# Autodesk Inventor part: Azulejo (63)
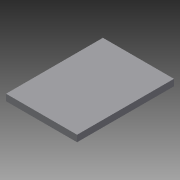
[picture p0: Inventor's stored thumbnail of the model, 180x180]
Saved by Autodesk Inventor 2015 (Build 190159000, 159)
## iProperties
Created: 2015-04
Part Number: Azulejo (63)
Material: Genérico
Document SubType Name: Modeling
Designer: Felipe
Density: 1 g/cm^3
Appearance: Padrão
Author: Felipe
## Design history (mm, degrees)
sketch "Sketch1"
  geometry: L1 (331.131, 3222.232)-(331.131, 2322.232); L2 (-328.869, 3222.232)-(331.131, 3222.232); L3 (-328.869, 2322.232)-(331.131, 2322.232); L4 (-328.869, -3617.768)-(-328.869, 3222.232); 1 further point
  constraints: 8 end point, 1 point on line
  dimensions: "d2" = 660 distance between parallel lines of L1 L4; "d3" = 900 distance between parallel lines of L2 L3
extrude "Extrusion1" new body sketch "Sketch1" distance "d0" = 60; taper "d1" = 0 deg
body "Solid1"
